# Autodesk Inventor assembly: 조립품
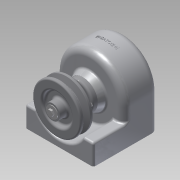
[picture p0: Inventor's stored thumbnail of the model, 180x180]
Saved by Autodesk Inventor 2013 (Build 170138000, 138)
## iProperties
Created: 2015-02
Part Number: 조립품
Document SubType Name: Assembly
Designer: Administrator
Author: Administrator
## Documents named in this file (14)
- C:\Users\Administrator\Desktop\450216V1023\조립품.iam
- C:\Users\Administrator\Desktop\450216V1023\본체.ipt
- C:\Users\Administrator\Desktop\450216V1023\축커버.ipt
- C:\Users\Administrator\Desktop\450216V1023\베어링 6001.ipt
- C:\Users\Administrator\Desktop\450216V1023\오일실.ipt
- C:\Users\Administrator\Desktop\450216V1023\축.ipt
- C:\Users\Administrator\Desktop\450216V1023\키5x5.ipt
- C:\Users\Administrator\Desktop\450216V1023\키4x4.ipt
- C:\Users\Administrator\Desktop\450216V1023\스퍼기어.ipt
- C:\Users\Administrator\Desktop\450216V1023\M3x0.5.ipt
- C:\Users\Administrator\Desktop\450216V1023\V-벨트풀리.ipt
- C:\Users\Administrator\Desktop\450216V1023\M5x0.8.ipt
- M5x0.8.ipt
- C:\Users\Administrator\Desktop\450216V1023\와샤.ipt
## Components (6 placed, 3 different names)
1. V-벨트풀리:1
2. M5x0.8:1
3. M3x0.5:1
4. M3x0.5:2
5. M3x0.5:3
6. M3x0.5:4
